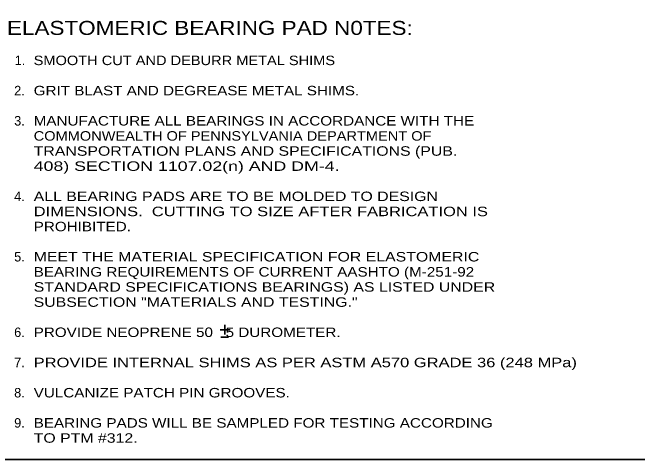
# Model space of a CAD drawing. Extents: x -11 to 79, y -154 to 0.
# Drawn here: x 51.83 to 59.74, y -65.25 to -59.59 of the extents above; entities that cross this region are included whole.
import ezdxf
from ezdxf.enums import TextEntityAlignment as Align

# ---------------------------------------------------------------- set-up
doc = ezdxf.new("R2010")
doc.units = 0
doc.header["$LTSCALE"] = 0.048
doc.layers.add('1', color=7, linetype='Continuous', lineweight=25)
doc.layers.add('3', color=7, linetype='Continuous', lineweight=25)

msp = doc.modelspace()

# ---------------------------------------------------------------- linework, layer by layer
at = {"layer": '1', "lineweight": 35}
msp.add_lwpolyline([(35.75, -65.25), (67.25, -65.25), (67.25, -44.75), (35.75, -44.75)], close=True, dxfattribs=at)
at = {"layer": '3', "lineweight": 35}
for p, q in [((54.52308, -63.6685), (54.52308, -63.54542)), ((54.46275, -63.60817), (54.58825, -63.60817)), ((54.47242, -63.69992), (54.5665, -63.69992))]:
    msp.add_line(p, q, dxfattribs=at)

# ---------------------------------------------------------------- texts
at = {"layer": '3'}
for s, height, width, p in [('ELASTOMERIC BEARING PAD N0TES:', 0.1772, 1.2, (51.76425, -59.87475)), ('SMOOTH CUT AND DEBURR METAL SHIMS', 0.12, 1.15, (52.10225, -60.25717)), ('GRIT BLAST AND DEGREASE METAL SHIMS.', 0.12, 1.2, (52.10225, -60.63967)), ('MANUFACTURE ALL BEARINGS IN ACCORDANCE WITH THE', 0.12, 1.2, (52.10225, -61.02208)), ('COMMONWEALTH OF PENNSYLVANIA DEPARTMENT OF', 0.12, 1.15, (52.10225, -61.21333)), ('TRANSPORTATION PLANS AND SPECIFICATIONS (PUB.', 0.12, 1.25, (52.10225, -61.4045)), ('408) SECTION 1107.02(n) AND DM-4.', 0.12, 1.4, (52.10225, -61.59575)), ('ALL BEARING PADS ARE TO BE MOLDED TO DESIGN', 0.12, 1.25, (52.10225, -61.97825)), ('DIMENSIONS.  CUTTING TO SIZE AFTER FABRICATION IS', 0.12, 1.3, (52.10225, -62.16942)), ('PROHIBITED.', 0.12, 1.2, (52.10225, -62.36067)), ('MEET THE MATERIAL SPECIFICATION FOR ELASTOMERIC', 0.12, 1.25, (52.10225, -62.74308)), ('BEARING REQUIREMENTS OF CURRENT AASHTO (M-251-92', 0.12, 1.2, (52.10225, -62.93433)), ('STANDARD SPECIFICATIONS BEARINGS) AS LISTED UNDER', 0.12, 1.25, (52.10225, -63.12558)), ('SUBSECTION "MATERIALS AND TESTING."', 0.12, 1.25, (52.10225, -63.31683)), ('PROVIDE NEOPRENE 50   5 DUROMETER.', 0.12, 1.2, (52.10225, -63.69925)), ('PROVIDE INTERNAL SHIMS AS PER ASTM A570 GRADE 36 (248 MPa)', 0.12, 1.3, (52.10225, -64.08167)), ('VULCANIZE PATCH PIN GROOVES.', 0.12, 1.2, (52.10225, -64.46417)), ('BEARING PADS WILL BE SAMPLED FOR TESTING ACCORDING', 0.12, 1.2, (52.10225, -64.84658)), ('TO PTM #312.', 0.12, 1.25, (52.10225, -65.03783))]:
    msp.add_text(s, height=height, dxfattribs=dict(at, width=width)).set_placement(p)
for s, p in [('1.', (51.99592, -60.25717)), ('2.', (51.98917, -60.63967)), ('3.', (51.98917, -61.02208)), ('4.', (51.98917, -61.97825)), ('5.', (51.98917, -62.74308)), ('6.', (51.98917, -63.69925)), ('7.', (51.98917, -64.08167)), ('8.', (51.98917, -64.46417)), ('9.', (51.98917, -64.84658))]:
    msp.add_text(s, height=0.12, dxfattribs=at).set_placement(p, align=Align.RIGHT)

doc.saveas('drawing.dxf')
